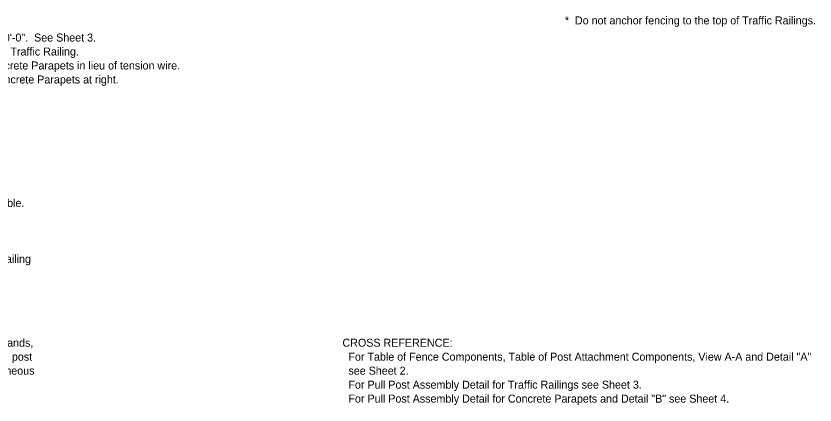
# Model space of a CAD drawing. Extents: x 0.2 to 40.8, y 0.5 to 25.7.
# Drawn here: x 16.13 to 36.25, y 0.47 to 10.27 of the extents above; entities that cross this region are included whole.
import ezdxf

# ---------------------------------------------------------------- set-up
doc = ezdxf.new("R2010")
doc.units = 0
doc.layers.add('Dimension', color=7, linetype='Continuous')

msp = doc.modelspace()

# ---------------------------------------------------------------- texts
at = {"layer": 'Dimension'}
for s, p in [('*  Do not anchor fencing to the top of Traffic Railings.', (29.947, 10.057)), ('  1.  A Pull Post Assembly is required at maximum intervals of 500\'-0".  See Sheet 3.', (8.106, 9.625)), ('  2.  Brace rails are only required for vertical fence installations on Traffic Railing.  ', (8.106, 9.273)), ('  3.  Provide horizontal rails for vertical fence installations on Concrete Parapets in lieu of tension wire.  ', (8.106, 8.921)), ('      Locate horizontal rails as shown in the Typical Section for Concrete Parapets at right.', (8.106, 8.569)), ('CROSS REFERENCE:', (24.348, 1.937)), ('  For Table of Fence Components, Table of Post Attachment Components, View A-A and Detail "A"', (24.348, 1.585)), ('  see Sheet 2.', (24.348, 1.233)), ('  For Pull Post Assembly Detail for Traffic Railings see Sheet 3.', (24.348, 0.881)), ('  For Pull Post Assembly Detail for Concrete Parapets and Detail "B" see Sheet 4.', (24.348, 0.529))]:
    msp.add_text(s, height=0.2016, dxfattribs=at).set_placement(p)
for s, p in [('  thickness of shim plates will be determined in the field.  Install chain link fence in accordance with ASTM F567 as applicable.', (1.369, 5.457)), ('  See Index 521-820 - Pedestrian/Bicycle Railing for Concrete Parapet details.  Provide fencing in lieu of aluminum bullet railing ', (1.369, 4.049)), ('  Payment will be made under Fencing, Type R.  Payment includes posts, horizontal and expansion rails, brace rails and bands,', (1.369, 1.937)), ('  rail ends, combination rail ends, boulevard clamps, chain link fabric, tension wire, ties, hog rings, tension bars and bands, post', (1.369, 1.585)), ('  and loop caps, pipe clamps, base plates, anchor rods, bolts, nuts, washers, shim plates, spacers, bearing pads, miscellaneous', (1.369, 1.233))]:
    msp.add_text(s, height=0.2016, rotation=0, dxfattribs=at).set_placement(p)

doc.saveas('drawing.dxf')
